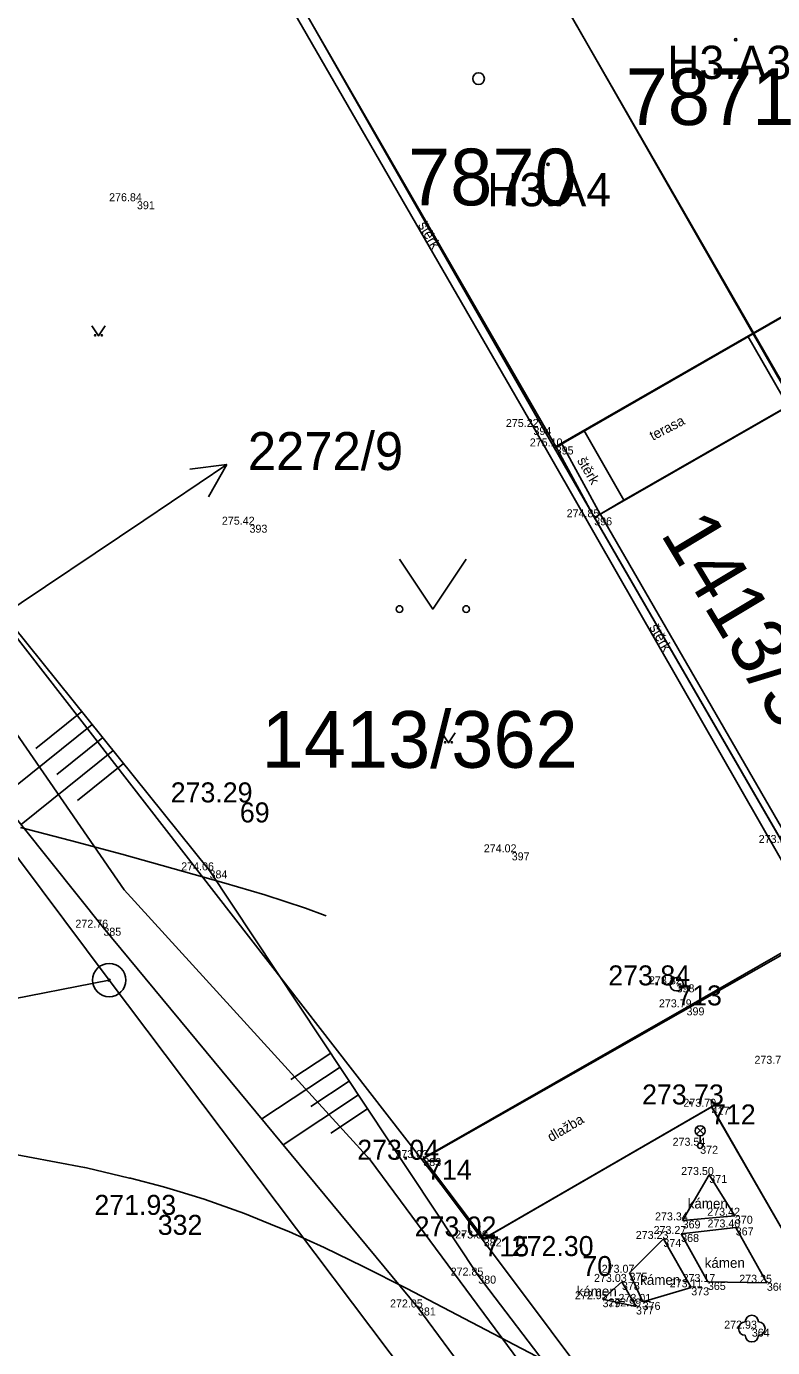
# Model space of a CAD drawing. Extents: x -771260 to -770828, y -1053564 to -1052811.
# Drawn here: x -770997.95 to -770975.57, y -1053197.5 to -1053157.87 of the extents above; entities that cross this region are included whole.
import ezdxf

# ---------------------------------------------------------------- set-up
doc = ezdxf.new("R2010")
doc.units = 0
for name, color, linetype in [('25_10_2019_budova', 7, 'Continuous'), ('25_10_2019_dlazba', 7, 'Continuous'), ('25_10_2019_hrana', 7, 'Continuous'), ('25_10_2019_kameny', 7, 'Continuous'), ('25_10_2019_lampa', 7, 'Continuous'), ('25_10_2019_operna_stena', 7, 'Continuous'), ('25_10_2019_pata', 7, 'Continuous'), ('25_10_2019_popis_objektu', 7, 'Continuous'), ('25_10_2019_popis_povrchu', 7, 'Continuous'), ('25_10_2019_sachta', 7, 'Continuous'), ('25_10_2019_srafy', 7, 'Continuous'), ('25_10_2019_sterk', 7, 'Continuous'), ('25_10_2019_strom', 7, 'Continuous'), ('25_10_2019_terasa', 7, 'Continuous'), ('25_10_2019_zamereny_bod', 7, 'Continuous'), ('25_10_2019_zamereny_bod_cislo', 7, 'Continuous'), ('25_10_2019_zamereny_bod_vyska', 7, 'Continuous'), ('25_10_2019_znacka_budovy', 7, 'Continuous'), ('25_10_2019_znacka_zelen', 7, 'Continuous'), ('25_3_2019_vrstevnice_interval_po_1m', 7, 'Continuous'), ('25_3_2019_zamereny_bod', 7, 'Continuous'), ('25_3_2019_zamereny_bod_cislo', 7, 'Continuous'), ('25_3_2019_zamereny_bod_vyska', 7, 'Continuous'), ('6_8_2021_zamereny_bod', 7, 'Continuous'), ('6_8_2021_zamereny_bod_cislo', 7, 'Continuous'), ('6_8_2021_zamereny_bod_vyska', 7, 'Continuous'), ('Default', 7, 'Continuous'), ('DKM_Hranice parcel', 7, 'Continuous'), ('DKM_Parcelní čísla', 7, 'Continuous'), ('DKM_Pop  PČ popisy', 7, 'Continuous'), ('DKM_Vnitřní kresba', 7, 'Continuous'), ('DKM_Značky bodu BP', 7, 'Continuous'), ('DKM_Značky budov', 7, 'Continuous'), ('DKM_Značky kultur', 7, 'Continuous')]:
    doc.layers.add(name, color=color, linetype=linetype)

# ---------------------------------------------------------------- blocks, each defined once
blk = doc.blocks.new('POINT_DISPLAY')
at = {"layer": 'Default'}
blk.add_line((0, 0), (0, 0), dxfattribs=at)
blk = doc.blocks.new('6.200')
at = {"layer": '25_10_2019_sachta'}
blk.add_circle((0, 0), 10, dxfattribs=at)
blk = doc.blocks.new('6.560')
at = {"layer": '25_10_2019_lampa'}
for p, q in [((-5.3, 17.2), (5.3, 27.8)), ((5.4, 17.3), (-5.1, 27.9)), ((0, 4), (0, 15))]:
    blk.add_line(p, q, dxfattribs=at)
for centre, radius in [((0, 22.5), 7.5), ((0, 0), 4), ((0, 0), 4)]:
    blk.add_circle(centre, radius, dxfattribs=at)
blk = doc.blocks.new('3.130')
at = {"layer": '25_10_2019_strom'}
blk.add_circle((0, 0), 0.01, dxfattribs=at)
for centre, start, end in [((0, 10), 0, 180), ((-10, 0), 90, 270), ((10, 0), 270, 90), ((0, -10), 180, 360)]:
    blk.add_arc(centre, 10, start, end, dxfattribs=at)
blk = doc.blocks.new('4.020')
at = {"layer": '25_10_2019_znacka_budovy'}
blk.add_circle((0, 0), 1.75, dxfattribs=at)
blk = doc.blocks.new('3.140')
at = {"layer": '25_10_2019_znacka_zelen'}
blk.add_lwpolyline([(-10, 15), (0, 0), (10, 15)], dxfattribs=at)
for centre in [(-5, 1), (-5, 1), (5, 1), (5, 1)]:
    blk.add_circle(centre, 1, dxfattribs=at)

msp = doc.modelspace()

# ---------------------------------------------------------------- linework, layer by layer
at = {"layer": '25_10_2019_budova'}
for p, q in [((-770976.138, -1053167.065), (-770983.884, -1053153.595)), ((-770982.073, -1053170.471), (-770989.826, -1053157.012)), ((-770982.073, -1053170.471), (-770958.667, -1053157.037))]:
    msp.add_line(p, q, dxfattribs=at)
at = {"layer": '25_10_2019_dlazba'}
for p, q in [((-770978.147, -1053187.297), (-770973.847, -1053184.824)), ((-770986.046, -1053191.816), (-770978.147, -1053187.297)), ((-770984.231, -1053194.229), (-770977.395, -1053190.28)), ((-770977.395, -1053190.28), (-770957.487, -1053224.903)), ((-770986.046, -1053191.816), (-770984.231, -1053194.229))]:
    msp.add_line(p, q, dxfattribs=at)
at = {"layer": '25_10_2019_hrana'}
for p, q in [((-771000.209, -1053173.555), (-770992.458, -1053183.188)), ((-770992.458, -1053183.188), (-770984.397, -1053195.344)), ((-770984.397, -1053195.344), (-770976.246, -1053206.028))]:
    msp.add_line(p, q, dxfattribs=at)
at = {"layer": '25_10_2019_kameny'}
for p, q in [((-770977.464, -1053192.325), (-770978.264, -1053193.688)), ((-770976.697, -1053193.548), (-770977.464, -1053192.325)), ((-770978.264, -1053193.688), (-770976.697, -1053193.548)), ((-770976.672, -1053193.899), (-770978.308, -1053194.095)), ((-770975.738, -1053195.558), (-770976.672, -1053193.899)), ((-770978.842, -1053194.244), (-770979.856, -1053195.259)), ((-770978.006, -1053195.696), (-770978.842, -1053194.244)), ((-770978.308, -1053194.095), (-770977.506, -1053195.535)), ((-770980.085, -1053195.533), (-770980.666, -1053196.05)), ((-770979.664, -1053196.269), (-770980.085, -1053195.533)), ((-770979.856, -1053195.259), (-770979.463, -1053196.132)), ((-770977.506, -1053195.535), (-770975.738, -1053195.558)), ((-770979.463, -1053196.132), (-770978.006, -1053195.696)), ((-770980.666, -1053196.05), (-770979.664, -1053196.269))]:
    msp.add_line(p, q, dxfattribs=at)
at = {"layer": '25_10_2019_operna_stena'}
for p, q in [((-770968.137, -1053181.407), (-770976.311, -1053167.164)), ((-770967.863, -1053181.482), (-770976.138, -1053167.065)), ((-770982.073, -1053170.471), (-770980.916, -1053172.597)), ((-770981.897, -1053170.376), (-770980.741, -1053172.501)), ((-770980.743, -1053172.497), (-770973.638, -1053184.785)), ((-770980.916, -1053172.597), (-770973.811, -1053184.886))]:
    msp.add_line(p, q, dxfattribs=at)
at = {"layer": '25_10_2019_pata'}
for p, q in [((-770995.643, -1053184.907), (-771002.649, -1053176.137)), ((-770986.206, -1053196.3), (-770995.643, -1053184.907)), ((-770978.37, -1053206.93), (-770986.206, -1053196.3))]:
    msp.add_line(p, q, dxfattribs=at)
at = {"layer": '25_10_2019_srafy'}
for p, q in [((-770996.292, -1053178.423), (-770997.671, -1053179.533)), ((-770995.978, -1053178.813), (-770998.738, -1053181.033)), ((-770995.665, -1053179.202), (-770997.045, -1053180.313)), ((-770995.352, -1053179.592), (-770998.114, -1053181.815)), ((-770995.038, -1053179.981), (-770996.42, -1053181.093)), ((-770988.82, -1053188.673), (-770990.015, -1053189.466)), ((-770988.544, -1053189.09), (-770990.89, -1053190.646)), ((-770988.268, -1053189.507), (-770989.418, -1053190.27)), ((-770987.991, -1053189.923), (-770990.248, -1053191.42)), ((-770987.715, -1053190.34), (-770988.821, -1053191.074))]:
    msp.add_line(p, q, dxfattribs=at)
at = {"layer": '25_10_2019_sterk'}
for p, q in [((-770990.08, -1053157.188), (-770982.74, -1053169.889)), ((-770982.74, -1053169.889), (-770974.104, -1053184.972)), ((-770980.743, -1053172.498), (-770980.025, -1053172.086))]:
    msp.add_line(p, q, dxfattribs=at)
at = {"layer": '25_10_2019_terasa'}
for p, q in [((-770980.025, -1053172.086), (-770975.107, -1053169.261)), ((-770981.232, -1053169.988), (-770980.025, -1053172.086))]:
    msp.add_line(p, q, dxfattribs=at)
at = {"layer": '25_3_2019_vrstevnice_interval_po_1m'}
for points in [[(-770998.131, -1053181.903), (-770996.627, -1053182.291), (-770995.092, -1053182.704), (-770992.03, -1053183.564), (-770992.029, -1053183.564), (-770990.802, -1053183.924), (-770989.584, -1053184.326), (-770988.988, -1053184.541), (-770988.959, -1053184.552)], [(-770996.627, -1053182.291), (-770996.627, -1053182.291)], [(-770995.092, -1053182.704), (-770995.092, -1053182.704)], [(-770992.029, -1053183.564), (-770992.029, -1053183.564)], [(-770990.802, -1053183.924), (-770990.802, -1053183.924)], [(-770989.584, -1053184.326), (-770989.584, -1053184.326)], [(-770988.959, -1053184.552), (-770988.959, -1053184.552)], [(-770988.959, -1053184.552), (-770988.959, -1053184.552)], [(-770999.623, -1053191.458), (-770996.207, -1053192.099), (-770996.154, -1053192.11), (-770994.861, -1053192.418), (-770994.835, -1053192.424), (-770993.845, -1053192.68), (-770993.845, -1053192.681), (-770993.337, -1053192.826), (-770992.619, -1053193.046), (-770991.407, -1053193.479), (-770990.463, -1053193.866), (-770990.083, -1053194.022), (-770989.024, -1053194.503), (-770987.848, -1053195.069), (-770986.54, -1053195.727), (-770982.01, -1053198.104), (-770979.748, -1053199.226), (-770978.624, -1053199.817), (-770977.983, -1053200.165), (-770977.956, -1053200.18)], [(-770996.154, -1053192.11), (-770996.154, -1053192.11)], [(-770994.835, -1053192.424), (-770994.835, -1053192.424)], [(-770993.845, -1053192.681), (-770993.845, -1053192.681)], [(-770993.337, -1053192.826), (-770993.337, -1053192.826)], [(-770992.619, -1053193.046), (-770992.619, -1053193.046)], [(-770991.407, -1053193.479), (-770991.407, -1053193.479)], [(-770990.083, -1053194.022), (-770990.083, -1053194.022)], [(-770989.024, -1053194.503), (-770989.024, -1053194.503)], [(-770987.848, -1053195.069), (-770987.848, -1053195.069)], [(-770986.54, -1053195.727), (-770986.54, -1053195.727)]]:
    msp.add_lwpolyline(points, dxfattribs=at)
at = {"layer": 'DKM_Hranice parcel'}
for p, q in [((-771008.68, -1053168.83), (-770995.47, -1053186.48)), ((-770980.91, -1053172.6), (-770974.95, -1053169.18)), ((-770980.91, -1053172.6), (-770973.81, -1053184.88)), ((-770973.81, -1053184.88), (-770986.09, -1053191.86)), ((-771022.83, -1053191.81), (-770995.47, -1053186.48)), ((-770995.47, -1053186.48), (-770977.19, -1053210.73))]:
    msp.add_line(p, q, dxfattribs=at)
for points in [[(-770974.95, -1053169.18), (-770976.15, -1053167.09), (-770983.87, -1053153.59), (-770986.96, -1053148.18)], [(-770992.91, -1053151.6), (-770989.82, -1053157.02), (-770982.11, -1053170.52), (-770980.91, -1053172.6)], [(-770986.09, -1053191.86), (-771005.65, -1053166.67), (-771007.81, -1053163.9)], [(-770974.57, -1053209.54), (-770987.64, -1053191.87), (-770995.02, -1053183.77), (-771005.13, -1053169.12)], [(-770984.27, -1053194.26), (-770977.39, -1053190.28), (-770957.49, -1053224.9), (-770960.18, -1053226.44)], [(-770984.27, -1053194.26), (-770985.51, -1053192.61), (-770986.09, -1053191.86)], [(-770960.18, -1053226.44), (-770967.88, -1053216.14), (-770984.27, -1053194.26)]]:
    msp.add_lwpolyline(points, dxfattribs=at)
at = {"layer": 'DKM_Pop  PČ popisy'}
for p, q in [((-770994.43, -1053172.69), (-770991.942, -1053171.012)), ((-770991.942, -1053171.012), (-770993.052, -1053171.157)), ((-770991.942, -1053171.012), (-770992.492, -1053171.987)), ((-770999.21, -1053175.9), (-770994.43, -1053172.69))]:
    msp.add_line(p, q, dxfattribs=at)
at = {"layer": 'DKM_Vnitřní kresba'}
for p, q in [((-770976.15, -1053167.09), (-770970.39, -1053163.77)), ((-770982.11, -1053170.52), (-770976.15, -1053167.09))]:
    msp.add_line(p, q, dxfattribs=at)
at = {"layer": 'DKM_Značky bodu BP'}
for radius in [0.5, 0.0303]:
    msp.add_circle((-770995.47, -1053186.48), radius, dxfattribs=at)
at = {"layer": 'DKM_Značky budov'}
msp.add_circle((-770984.387, -1053159.439), 0.175, dxfattribs=at)
at = {"layer": 'DKM_Značky kultur'}
msp.add_lwpolyline([(-770986.76, -1053173.849), (-770985.76, -1053175.35), (-770984.76, -1053173.849)], dxfattribs=at)
for centre in [(-770986.76, -1053175.349), (-770984.76, -1053175.349)]:
    msp.add_circle(centre, 0.1, dxfattribs=at)

# ---------------------------------------------------------------- block references
at = {"layer": '25_10_2019_lampa', "xscale": 0.020000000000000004, "yscale": 0.020000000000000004}
msp.add_blockref('6.560', (-770977.738, -1053191.449), dxfattribs=at)
at = {"layer": '25_10_2019_sachta', "xscale": 0.020000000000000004, "yscale": 0.020000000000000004}
msp.add_blockref('6.200', (-770978.446, -1053186.606), dxfattribs=at)
at = {"layer": '25_10_2019_strom', "xscale": 0.020000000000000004, "yscale": 0.020000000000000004}
msp.add_blockref('3.130', (-770976.189, -1053196.935), dxfattribs=at)
at = {"layer": '25_10_2019_zamereny_bod', "xscale": 0.1, "yscale": 0.10000000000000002}
for p in [(-770994.637, -1053163.116), (-770982.74, -1053169.889), (-770982.073, -1053170.471), (-770991.26, -1053172.819), (-770980.917, -1053172.597), (-770983.393, -1053182.647), (-770992.459, -1053183.188), (-770995.644, -1053184.908), (-770978.446, -1053186.606), (-770978.147, -1053187.297), (-770977.396, -1053190.28), (-770977.738, -1053191.449), (-770986.046, -1053191.817), (-770977.464, -1053192.326), (-770976.697, -1053193.548), (-770978.265, -1053193.688), (-770976.672, -1053193.899), (-770984.232, -1053194.23), (-770978.843, -1053194.245), (-770978.309, -1053194.095), (-770984.397, -1053195.344), (-770980.086, -1053195.533), (-770979.857, -1053195.259), (-770977.507, -1053195.535), (-770978.006, -1053195.696), (-770975.738, -1053195.559), (-770986.206, -1053196.3), (-770980.667, -1053196.051), (-770979.664, -1053196.27), (-770979.464, -1053196.133), (-770976.189, -1053196.935)]:
    msp.add_blockref('POINT_DISPLAY', p, dxfattribs=at)
at = {"layer": '25_10_2019_znacka_budovy', "xscale": 0.020000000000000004, "yscale": 0.020000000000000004}
for p in [(-770976.673, -1053158.274), (-770982.304, -1053162.009)]:
    msp.add_blockref('4.020', p, dxfattribs=at)
at = {"layer": '25_10_2019_znacka_zelen', "xscale": 0.020000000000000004, "yscale": 0.020000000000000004}
for p in [(-770995.791, -1053167.156), (-770985.29, -1053179.366)]:
    msp.add_blockref('3.140', p, dxfattribs=at)
at = {"layer": '25_3_2019_zamereny_bod', "xscale": 0.1, "yscale": 0.10000000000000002}
for p in [(-770991.549, -1053181.149), (-770994.013, -1053193.522), (-770981.274, -1053194.757)]:
    msp.add_blockref('POINT_DISPLAY', p, dxfattribs=at)
at = {"layer": '6_8_2021_zamereny_bod', "xscale": 0.1, "yscale": 0.10000000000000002}
for p in [(-770978.425, -1053186.639), (-770977.412, -1053190.21), (-770985.931, -1053191.869), (-770984.209, -1053194.17)]:
    msp.add_blockref('POINT_DISPLAY', p, dxfattribs=at)

# ---------------------------------------------------------------- texts
at = {"layer": '25_10_2019_popis_objektu'}
for s, height, p in [('H3.A3', 1, (-770978.726, -1053159.451)), ('H3.A4', 1, (-770984.128, -1053163.266)), ('kámen', 0.3, (-770978.113, -1053193.33)), ('kámen', 0.3, (-770977.602, -1053195.11)), ('kámen', 0.3, (-770979.54, -1053195.621)), ('kámen', 0.3, (-770981.446, -1053195.963))]:
    msp.add_text(s, height=height, dxfattribs=at).set_placement(p)
msp.add_text('terasa', height=0.3, rotation=27.3269, dxfattribs=at).set_placement((-770979.161, -1053170.305))
at = {"layer": '25_10_2019_popis_povrchu'}
for s, rotation, p in [('štěrk', 300.687, (-770986.216, -1053163.832)), ('štěrk', 300.687, (-770981.441, -1053170.897)), ('štěrk', 300.687, (-770979.275, -1053175.902)), ('dlažba', 30.687, (-770982.212, -1053191.343))]:
    msp.add_text(s, height=0.3, rotation=rotation, dxfattribs=at).set_placement(p)
at = {"layer": '25_10_2019_zamereny_bod_cislo'}
for s, p in [('391', (-770994.637, -1053163.356)), ('394', (-770982.74, -1053170.129)), ('395', (-770982.073, -1053170.711)), ('393', (-770991.26, -1053173.059)), ('396', (-770980.917, -1053172.837)), ('397', (-770983.393, -1053182.887)), ('384', (-770992.459, -1053183.428)), ('385', (-770995.644, -1053185.148)), ('398', (-770978.446, -1053186.846)), ('399', (-770978.147, -1053187.537)), ('417', (-770977.396, -1053190.52)), ('372', (-770977.738, -1053191.689)), ('383', (-770986.046, -1053192.057)), ('371', (-770977.464, -1053192.566)), ('370', (-770976.697, -1053193.788)), ('369', (-770978.265, -1053193.928)), ('367', (-770976.672, -1053194.139)), ('382', (-770984.232, -1053194.47)), ('374', (-770978.843, -1053194.485)), ('368', (-770978.309, -1053194.335)), ('380', (-770984.397, -1053195.584)), ('378', (-770980.086, -1053195.773)), ('375', (-770979.857, -1053195.499)), ('365', (-770977.507, -1053195.775)), ('373', (-770978.006, -1053195.936)), ('366', (-770975.738, -1053195.799)), ('381', (-770986.206, -1053196.54)), ('379', (-770980.667, -1053196.291)), ('377', (-770979.664, -1053196.51)), ('376', (-770979.464, -1053196.373)), ('364', (-770976.189, -1053197.175))]:
    msp.add_text(s, height=0.24, dxfattribs=at).set_placement(p)
at = {"layer": '25_10_2019_zamereny_bod_vyska'}
for s, p in [('276.84 ', (-770995.472, -1053163.116)), ('275.22 ', (-770983.568, -1053169.889)), ('275.10 ', (-770982.851, -1053170.471)), ('274.85 ', (-770981.745, -1053172.597)), ('275.42 ', (-770992.088, -1053172.819)), ('274.02 ', (-770984.231, -1053182.647)), ('273.91 ', (-770975.983, -1053182.367)), ('274.06 ', (-770993.308, -1053183.188)), ('272.76 ', (-770996.483, -1053184.908)), ('273.82 ', (-770979.274, -1053186.606)), ('273.79 ', (-770978.976, -1053187.297)), ('273.73 ', (-770976.111, -1053188.99)), ('273.70 ', (-770978.242, -1053190.28)), ('273.03 ', (-770986.884, -1053191.817)), ('273.54 ', (-770978.566, -1053191.449)), ('273.50 ', (-770978.31, -1053192.326)), ('273.34 ', (-770979.093, -1053193.688)), ('273.42 ', (-770977.525, -1053193.548)), ('273.27 ', (-770979.136, -1053194.095)), ('273.40 ', (-770977.518, -1053193.899)), ('273.00 ', (-770985.088, -1053194.23)), ('273.23 ', (-770979.671, -1053194.245)), ('272.85 ', (-770985.225, -1053195.344)), ('273.07 ', (-770980.694, -1053195.259)), ('273.03 ', (-770980.924, -1053195.533)), ('273.11 ', (-770978.652, -1053195.696)), ('273.17 ', (-770978.266, -1053195.535)), ('273.25 ', (-770976.566, -1053195.559)), ('272.95 ', (-770981.496, -1053196.051)), ('273.01 ', (-770980.189, -1053196.133)), ('272.05 ', (-770987.044, -1053196.3)), ('272.99 ', (-770980.494, -1053196.27)), ('272.93 ', (-770977.018, -1053196.935))]:
    msp.add_text(s, height=0.24, dxfattribs=at).set_placement(p)
at = {"layer": '25_3_2019_zamereny_bod_cislo'}
for s, p in [('69', (-770991.549, -1053181.749)), ('332', (-770994.013, -1053194.122)), ('70', (-770981.274, -1053195.357))]:
    msp.add_text(s, height=0.6, dxfattribs=at).set_placement(p)
at = {"layer": '25_3_2019_zamereny_bod_vyska'}
for s, p in [('273.29 ', (-770993.623, -1053181.149)), ('271.93 ', (-770995.914, -1053193.522)), ('272.30 ', (-770983.391, -1053194.757))]:
    msp.add_text(s, height=0.6, dxfattribs=at).set_placement(p)
at = {"layer": '6_8_2021_zamereny_bod_cislo'}
for s, p in [('713', (-770978.425, -1053187.239)), ('712', (-770977.412, -1053190.81)), ('714', (-770985.931, -1053192.469)), ('715', (-770984.209, -1053194.77))]:
    msp.add_text(s, height=0.6, dxfattribs=at).set_placement(p)
at = {"layer": '6_8_2021_zamereny_bod_vyska'}
for s, p in [('273.84 ', (-770980.495, -1053186.639)), ('273.73 ', (-770979.482, -1053190.21)), ('273.04 ', (-770988.027, -1053191.869)), ('273.02 ', (-770986.305, -1053194.17))]:
    msp.add_text(s, height=0.6, dxfattribs=at).set_placement(p)
at = {"layer": 'DKM_Parcelní čísla'}
for s, height, p in [('7871', 1.7, (-770979.974, -1053160.83)), ('7870', 1.7, (-770986.504, -1053163.239)), ('2272/9', 1.139, (-770991.31, -1053171.179)), ('1413/362', 1.7, (-770990.895, -1053180.11))]:
    msp.add_text(s, height=height, dxfattribs=at).set_placement(p)
msp.add_text('1413/347', height=1.7, rotation=301, dxfattribs=at).set_placement((-770978.95, -1053173.091))

doc.saveas('drawing.dxf')
